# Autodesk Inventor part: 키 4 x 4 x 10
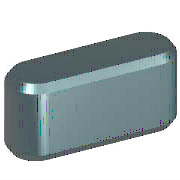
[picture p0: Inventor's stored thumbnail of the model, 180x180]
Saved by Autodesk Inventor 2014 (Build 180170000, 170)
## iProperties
IsCustomPart: 1
Created: 2012-02
Part Number: 키 4 x 4 x 10
Material: 강철, 연강
Description: 키 및 해당 키홈
Document SubType Name: Modeling
Standard: KS B 1311
Designer: test
Standards Organization: KS
Language: ko-KR
Size Designation: 4 x 4 x 10
Categories: <MemberInstance><Categories><Category DisplayName="샤프트 부품" InternalName="7f7aeb1f-a693-4053-b835-cee3144e0d98" Mnemonic="SHFT"><Category DisplayName="키" Interna
Density: 1 g/cm^3
Appearance: Yellow
Author: test
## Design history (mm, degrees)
sketch "스케치1"
  geometry: L1 (2, 2)-(8, 2); L2 (8, -2)-(2, -2); L3 (0, 9.4)-(0, -7.4) reference; L4 (-5, 0)-(30, 0) reference; L5 (10, 0)-(10, 7); A1 r 2 centre (2, 0) between (2, 2) and (2, -2); A2 r 2 centre (8, 0) between (8, -2) and (8, 2)
  constraints: 6 end point, 5 point on circle, 4 tangent, 3 point on line, 2 centre point, 1 horizontal, 1 parallel, 1 perpendicular
  dimensions: "d0" = 2 radius of A1 (= 0.5 x PB); "d13" = 2 radius of A2 (= 0.5 x PB); "d14" = 10 distance between parallel lines of L5 L3 (= NLG)
extrude "본체1" new body sketch "스케치1" taper "d3" = 0 deg; stored distance "d4" = 10
workplane "Work Plane3"
body "Solid1"
workplane "Work Plane1"
workplane "Work Plane2"
chamfer "모따기1" distance "d8" = 0.25 (= PHH); stored, may be unused: second distance "d9" = 0.25 (= PHH), angle "d15" = 45 deg
other parameters: "d1" = -2.5 (= -PNT), "d2" = 1.5 (= PH - PNT), "NLG" = 10 [user parameter; used in 3 equation terms], "PB" = 4 [user parameter; used in 2 equation terms], "PNT" = 2.5 [user parameter; used in 2 equation terms], "PH" = 4 [user parameter; used in 1 equation term], "PHH" = 0.25 [user parameter; used in 2 equation terms], "d10" = 0, "d16" = 0, "d17" = 0, "d18" = 0, "WDMAX" = 12 [user parameter], "RR" = 0.08 [user parameter], "PUEB" = 1.8 [user parameter]
